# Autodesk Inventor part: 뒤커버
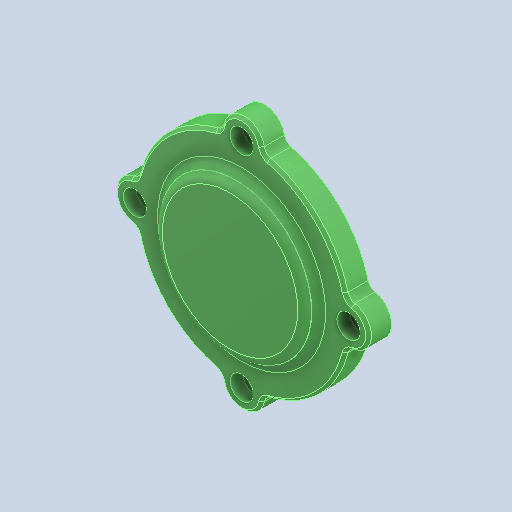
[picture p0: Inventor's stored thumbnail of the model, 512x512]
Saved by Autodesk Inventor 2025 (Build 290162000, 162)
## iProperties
Created: 2024-08
Part Number: 뒤커버
Material: 알루미늄 6061
Document SubType Name: Modeling
Designer: Administrator
Density: 2.71 g/cm^3
Appearance: 기본값
Company: 한국ATC센터
Author: jhkim
Sending System: Autodesk Inventor 2025
Preprocessor: ST-DEVELOPER v20
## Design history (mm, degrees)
feature "솔리드1"
node "솔리드2"
